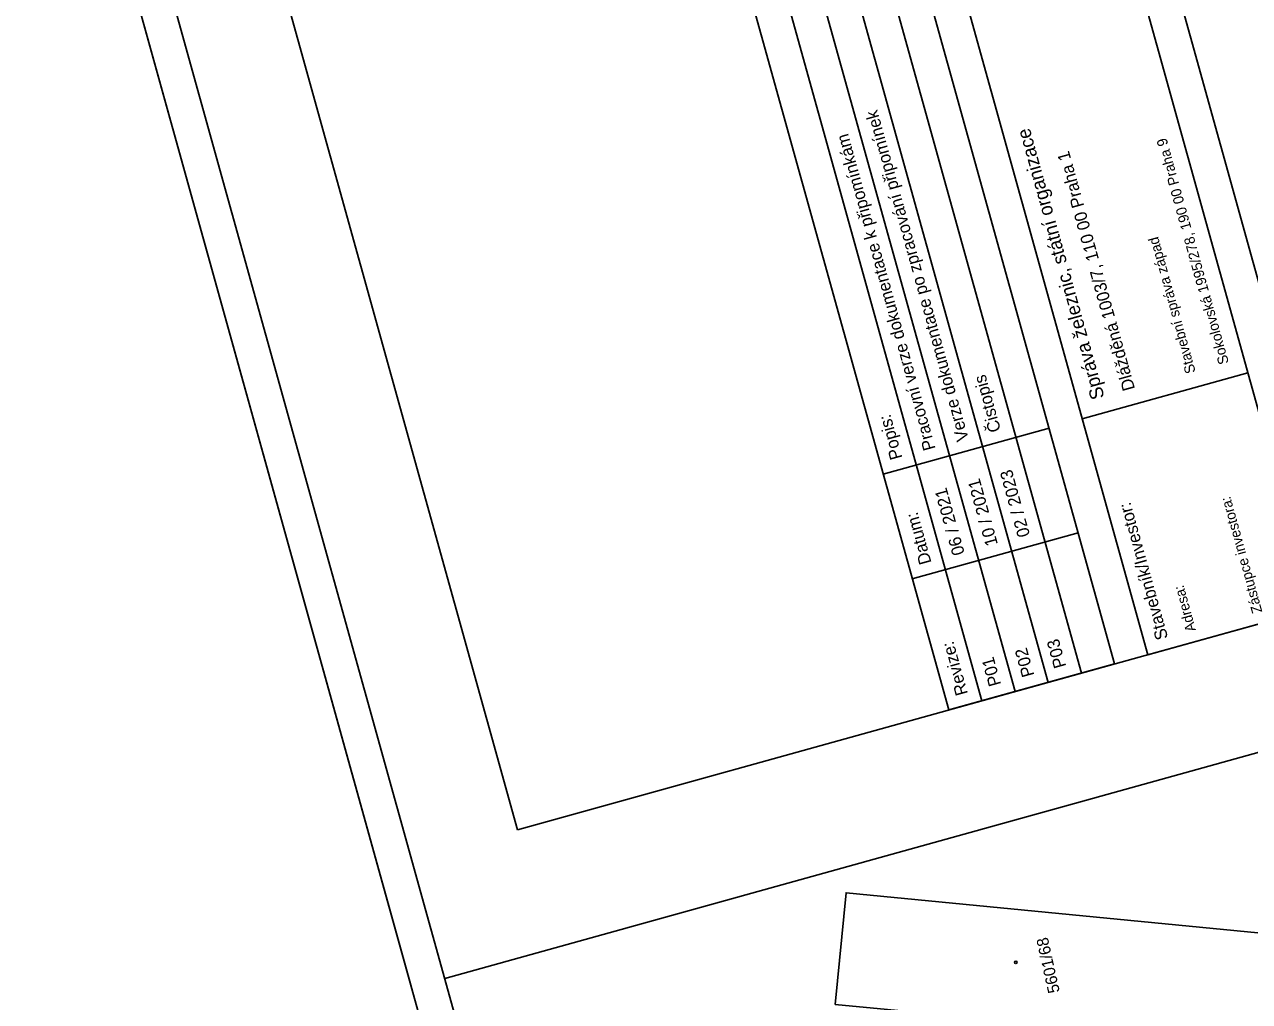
# Model space of a CAD drawing. Extents: x -821122 to -820555, y -1070892 to -1069801.
# Drawn here: x -821122.1 to -820944.2, y -1070085.1 to -1069943.1 of the extents above; entities that cross this region are included whole.
import ezdxf

# ---------------------------------------------------------------- set-up
doc = ezdxf.new("R2010")
doc.units = 0
for name, color, linetype in [('Hranice parcel', 7, 'Continuous'), ('Parcelní čísla', 7, 'Continuous'), ('Popisove_pole', 7, 'Continuous'), ('Ram', 7, 'Continuous'), ('Značky budov', 7, 'Continuous')]:
    doc.layers.add(name, color=color, linetype=linetype)

msp = doc.modelspace()

# ---------------------------------------------------------------- linework, layer by layer
at = {"layer": 'Hranice parcel'}
msp.add_lwpolyline([(-820942.5, -1070091.4), (-821004.34, -1070085.47), (-821002.76, -1070069.27), (-820940.94, -1070075.3), (-820942.5, -1070091.4)], dxfattribs=at)
at = {"layer": 'Popisove_pole'}
for p, q in [((-820973.4, -1070038.7), (-821018.91, -1069874.9)), ((-820968.58, -1070037.36), (-821014.09, -1069873.56)), ((-820978.21, -1070040.04), (-821023.73, -1069876.24)), ((-820983.03, -1070041.37), (-821028.55, -1069877.58)), ((-820944.38, -1069993.74), (-820968.46, -1070000.43)), ((-820973.28, -1070001.77), (-820997.37, -1070008.46)), ((-820969.05, -1070016.99), (-820993.14, -1070023.68))]:
    msp.add_line(p, q, dxfattribs=at)
for points in [[(-821050.48, -1070060.11), (-821095.99, -1069896.32), (-820845.48, -1069826.71), (-820799.97, -1069990.51)], [(-820930.04, -1070026.65), (-820975.55, -1069862.85), (-820927.38, -1069849.47), (-820881.87, -1070013.26)], [(-820958.94, -1070034.68), (-821004.46, -1069870.89), (-820980.37, -1069864.19), (-820934.86, -1070027.99)], [(-820987.85, -1070042.71), (-821033.36, -1069878.92), (-821009.28, -1069872.22), (-820963.76, -1070036.02)]]:
    msp.add_lwpolyline(points, close=True, dxfattribs=at)
at = {"layer": 'Ram'}
for points in [[(-821065.88, -1070083.04), (-821122.1, -1069880.71), (-820835.94, -1069801.19), (-820779.72, -1070003.53)], [(-820837.51, -1070886.22), (-821115.94, -1069884.19), (-820839.42, -1069807.35)], [(-820840.99, -1070892.38), (-821122.1, -1069880.71)], [(-820784.54, -1070004.87), (-821061.06, -1070081.7)]]:
    msp.add_lwpolyline(points, dxfattribs=at)
at = {"layer": 'Značky budov'}
msp.add_circle((-820978.1, -1070079.37), 0.175, dxfattribs=at)

# ---------------------------------------------------------------- texts
at = {"layer": 'Parcelní čísla'}
msp.add_text('5601/68', height=1.7, rotation=102.5197, dxfattribs=at).set_placement((-820971.7, -1070083.64))
at = {"layer": 'Popisove_pole'}
for s, height, p in [('Verze dokumentace po zpracování připomínek', 1.8, (-820984.92, -1070003.4)), ('Správa železnic, státní organizace', 2, (-820965.2, -1069997.29)), ('Pracovní verze dokumentace k připomínkám', 1.8, (-820989.74, -1070004.74)), ('Sokolovská 1995/278, 190 00 Praha 9', 1.5, (-820947.14, -1069992.28)), ('Dlážděná 1003/7, 110 00 Praha 1', 1.8, (-820960.77, -1069996.06)), ('Stavební správa západ', 1.5, (-820951.96, -1069993.61)), ('Čistopis', 1.8, (-820980.25, -1070002.1)), ('Popis:', 1.8, (-820994.56, -1070006.07)), ('02 / 2023', 1.8, (-820976.02, -1070017.32)), ('10 / 2021', 1.8, (-820980.69, -1070018.62)), ('06 / 2021', 1.8, (-820985.51, -1070019.96)), ('Zástupce investora:', 1.5, (-820942.28, -1070028.44)), ('Stavebník/Investor:', 1.8, (-820955.96, -1070032.25)), ('Datum:', 1.8, (-820990.33, -1070021.3)), ('Adresa:', 1.5, (-820951.91, -1070031.12)), ('Revize:', 1.8, (-820985.04, -1070040.33)), ('P03', 1.8, (-820970.76, -1070036.36)), ('P01', 1.8, (-820980.22, -1070038.99)), ('P02', 1.8, (-820975.4, -1070037.65))]:
    msp.add_text(s, height=height, rotation=105.5289, dxfattribs=at).set_placement(p)

doc.saveas('drawing.dxf')
